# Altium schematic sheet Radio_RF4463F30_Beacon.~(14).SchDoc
size A4
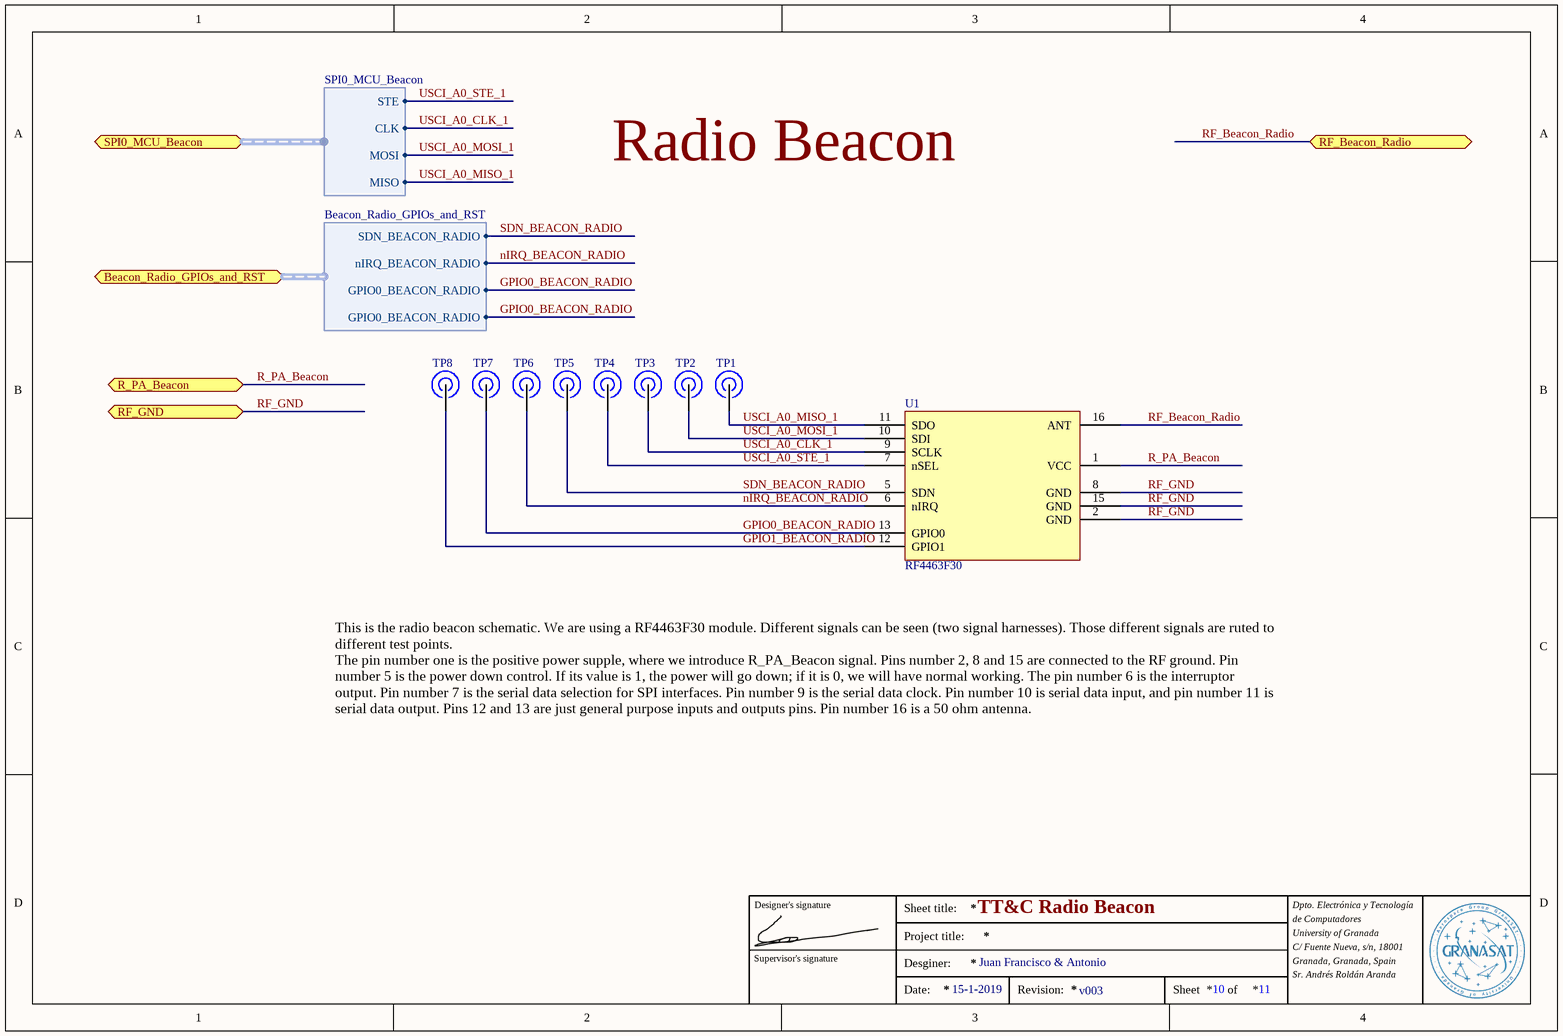
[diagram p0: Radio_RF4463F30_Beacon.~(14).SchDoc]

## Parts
TP1  TestPoint  [TESTPOINT_2x2mm]  (value not drawn)
TP2  TestPoint  [TESTPOINT_2x2mm]  (value not drawn)
TP3  TestPoint  [TESTPOINT_2x2mm]  (value not drawn)
TP4  TestPoint  [TESTPOINT_2x2mm]  (value not drawn)
TP5  TestPoint  [TESTPOINT_2x2mm]  (value not drawn)
TP6  TestPoint  [TESTPOINT_2x2mm]  (value not drawn)
TP7  TestPoint  [TESTPOINT_2x2mm]  (value not drawn)
TP8  TestPoint  [TESTPOINT_2x2mm]  (value not drawn)
U1  RF4463F30

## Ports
Beacon_Radio_GPIOs_and_RST (harness Beacon_Radio_GPIOs_and_RST), R_PA_Beacon, RF_Beacon_Radio, RF_GND, SPI0_MCU_Beacon (harness SPI0_MCU_Beacon)

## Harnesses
SPI0_MCU_Beacon: STE, CLK, MOSI, MISO
Beacon_Radio_GPIOs_and_RST: SDN_BEACON_RADIO, nIRQ_BEACON_RADIO, GPIO0_BEACON_RADIO, GPIO0_BEACON_RADIO

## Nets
GPIO0_BEACON_RADIO: TP7.1 U1.13(GPIO0) ; port Beacon_Radio_GPIOs_and_RST.GPIO0_BEACON_RADIO
GPIO1_BEACON_RADIO: TP8.1 U1.12(GPIO1)
nIRQ_BEACON_RADIO: TP6.1 U1.6(nIRQ) ; port Beacon_Radio_GPIOs_and_RST.nIRQ_BEACON_RADIO
R_PA_Beacon: U1.1(VCC) ; port R_PA_Beacon
RF_Beacon_Radio: U1.16(ANT) ; port RF_Beacon_Radio
RF_GND: U1.2(GND) U1.8(GND) U1.15(GND) ; port RF_GND
SDN_BEACON_RADIO: TP5.1 U1.5(SDN) ; port Beacon_Radio_GPIOs_and_RST.SDN_BEACON_RADIO
USCI_A0_CLK_1: TP3.1 U1.9(SCLK) ; port SPI0_MCU_Beacon.CLK
USCI_A0_MISO_1: TP1.1 U1.11(SDO) ; port SPI0_MCU_Beacon.MISO
USCI_A0_MOSI_1: TP2.1 U1.10(SDI) ; port SPI0_MCU_Beacon.MOSI
USCI_A0_STE_1: TP4.1 U1.7(nSEL) ; port SPI0_MCU_Beacon.STE

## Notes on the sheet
- Radio Beacon
- This is the radio beacon schematic. We are using a RF4463F30 module. Different signals can be seen (two signal harnesses). Those different signals are ruted to different test points.
  The pin number one is the positive power supple, where we introduce R_PA_Beacon signal. Pins number 2, 8 and 15 are connected to the RF ground. Pin number 5 is the power down control. If its value is 1, the power will go down; if it is 0, we will have normal working. The pin number 6 is the interruptor output. Pin number 7 is the serial data selection for SPI interfaces. Pin number 9 is the serial data clock. Pin number 10 is serial data input, and pin number 11 is serial data output. Pins 12 and 13 are just general purpose inputs and outputs pins. Pin number 16 is a 50 ohm antenna.
- Designer's signature
- Sheet title:
- TT&C Radio Beacon
- Dpto. Electrónica y Tecnología
- de Computadores
- Supervisor's signature
- Project title:
- Desginer:
- Juan Francisco & Antonio
- University of Granada
- C/ Fuente Nueva, s/n, 18001
- Granada, Granada, Spain
- Sr. Andrés Roldán Aranda
- Date:
- 15-1-2019
- Revision:
- v003
- Sheet
- 10
- of
- 11

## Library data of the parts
TP1-TP8 = TestPoint: Punto de prueba de 3x3mm; pin to pad: 1>TP; PCB DECAL: TestPoint XxXmm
